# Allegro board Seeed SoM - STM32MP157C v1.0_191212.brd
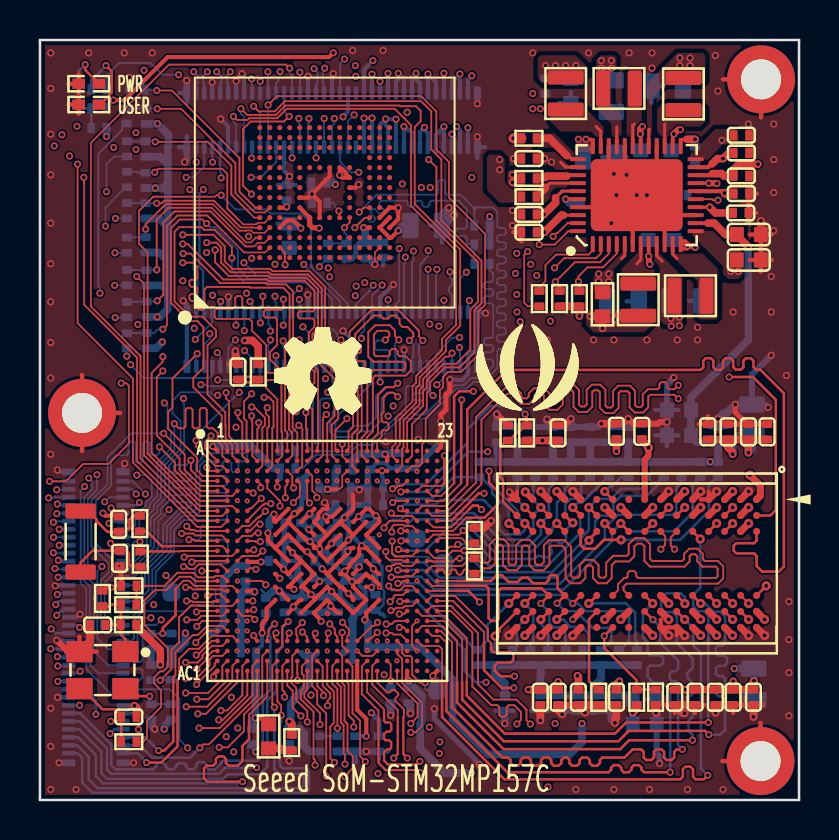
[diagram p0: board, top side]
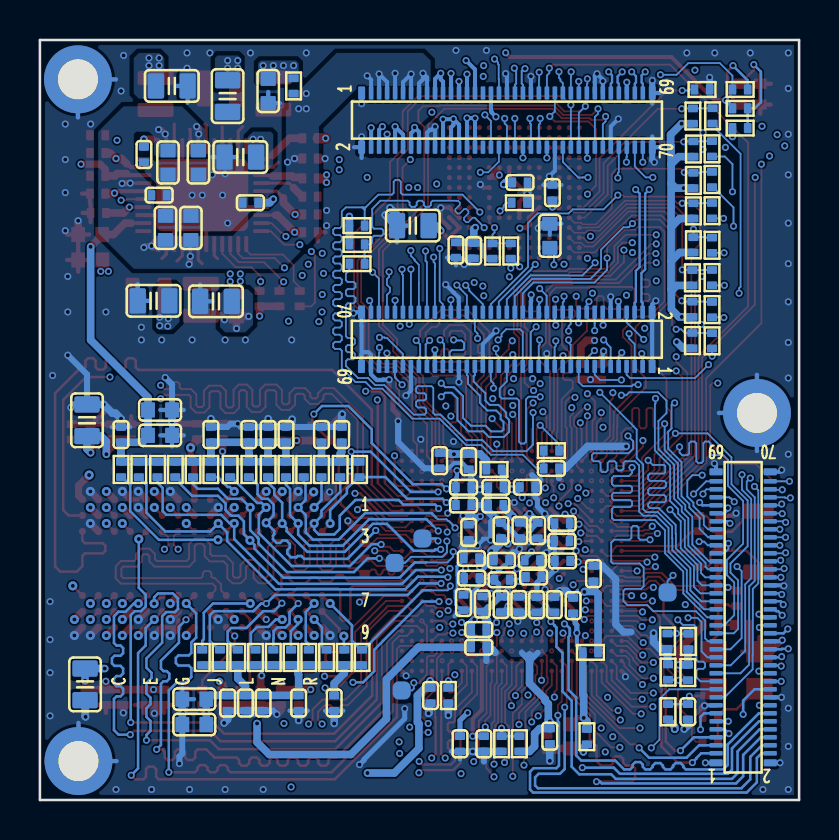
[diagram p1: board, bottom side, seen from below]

Outline 38 x 38 mm; copper layers: TOP, GND02, LAYER_3, PWR_4, LAYER_5, LAYER_6, GND7, BOTTOM. Coordinates in mm from the lower left corner of the outline.
Outline path: rectangle 38,0 0,38 ; 0,38 0,0 38,0 38,38 0,38

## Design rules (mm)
constraint set DEFAULT: min track width 0.089, pair gap 0.089
net group ADC1: nets ADC1_INN1 ADC1_INP1
net group DDR_CLK: nets DDR_CLK DDR_CLKN
net group DDR_DQS0: nets DDR_DQS0 DDR_DQSN0
net group DDR_DQS1: nets DDR_DQS1 DDR_DQSN1
net group DSI_CK: nets DSI_CK_N DSI_CK_P
net group DSI_D0: nets DSI_D0_N DSI_D0_P
net group DSI_D1: nets DSI_D1_N DSI_D1_P
net group ETH_MDC: nets ETH_MDC ETH_MDIO
net group OTG_FS: nets OTG_FS_DM OTG_FS_DP
net group USB1: nets USB1_N USB1_P
net group USB2: nets USB2_N USB2_P
net group DDR_A0: nets DDR_A0 DDR_A1 DDR_A2 DDR_A3 DDR_A4 DDR_A5 DDR_A6 DDR_A7 DDR_A8 DDR_A9 DDR_A10 DDR_A11 DDR_A12 DDR_A13 DDR_A14 DDR_BA0 DDR_BA1 DDR_BA2 DDR_CASN DDR_CKE DDR_CSN DDR_ODT DDR_RASN DDR_RESETN DDR_WEN
net group DDR_DQ0: nets DDR_D0 DDR_D1 DDR_D2 DDR_D3 DDR_D4 DDR_D5 DDR_D6 DDR_D7 DDR_DQM0
net group DDR_DQ1: nets DDR_D8 DDR_D9 DDR_D10 DDR_D11 DDR_D12 DDR_D13 DDR_D14 DDR_D15 DDR_DQM1
net group DVP: nets DVP_D0 DVP_D1 DVP_D2 DVP_D3 DVP_D4 DVP_D5 DVP_D6 DVP_D7 DVP_HSYNC DVP_PCLK DVP_VSYNC GPIO_PI3 SAI2_SDBM SPI5_MISO
net group ETH_RX: nets ETH_CLK125 ETH_RX_CLK ETH_RX_DV ETH_RXD0 ETH_RXD1 ETH_RXD2 ETH_RXD3
net group ETH_TX: nets ETH_GTX_CLK ETH_TX_EN ETH_TXD0 ETH_TXD1 ETH_TXD2 ETH_TXD3
net group LTDC: nets LTDC_B0 LTDC_B1 LTDC_B2 LTDC_B3 LTDC_B4 LTDC_B5 LTDC_B6 LTDC_B7 LTDC_CLK LTDC_DE LTDC_G0 LTDC_G1 LTDC_G2 LTDC_G3 LTDC_G4 LTDC_G5 LTDC_G6 LTDC_G7 LTDC_HSYNC LTDC_R0 LTDC_R1 LTDC_R2 LTDC_R3 LTDC_R4 LTDC_R5 LTDC_R6 LTDC_R7 LTDC_VSYNC
net group MMC2: nets MMC2_CLK MMC2_CMD MMC2_DAT0 MMC2_DAT1 MMC2_DAT2 MMC2_DAT3 MMC2_DAT4 MMC2_DAT5 MMC2_DAT6 MMC2_DAT7 N3283268
net group SDMMC1: nets SDMMC1_CK SDMMC1_CMD SDMMC1_D0 SDMMC1_D1 SDMMC1_D2 SDMMC1_D3
net group SDMMC3: nets SDMMC3_CLK SDMMC3_CMD SDMMC3_D0 SDMMC3_D1 SDMMC3_D2 SDMMC3_D3

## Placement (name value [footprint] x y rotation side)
C27  100nF  [C0402]  18.44 5.22 270 bottom
C28  1uF  [C0402]  11.87 12.94 0 bottom
C29  1uF  [C0402]  15.85 9.8 270 bottom
C30  1uF  [C0402]  11.86 13.83 0 bottom
C31  1uF  [C0402]  13.35 11.98 180 bottom
C32  1uF  [C0402]  13.08 13.47 270 bottom
C33  1uF  [C0402]  13.97 13.48 270 bottom
C34  1uF  [C0402]  14.92 13.47 90 bottom
C35  1uF  [C0402]  14.9 11.98 180 bottom
C36  1uF  [C0402]  14.92 9.78 90 bottom
C37  1uF  [C0402]  14.03 9.77 90 bottom
C38  1uF  [C0402]  12.25 9.77 90 bottom
C39  1uF  [C0402]  13.14 9.76 90 bottom
C40  1uF  [C0402]  14.87 11.01 0 bottom
C41  1uF  [C0402]  13.29 11.14 180 bottom
C42  1uF  [C0402]  16.38 11.09 180 bottom
C43  1uF  [C0402]  16.54 13.38 270 bottom
C44  1uF  [C0402]  16.8 9.87 270 bottom
C45  1uF  [C0402]  16.03 8.53 180 bottom
C46  1uF  [C0402]  11.31 9.72 90 bottom
C47  1uF  [C0402]  10.29 11.32 90 bottom
C48  1uF  [C0402]  15.78 2.81 90 bottom
C49  1uF  [C0402]  13.59 15.64 180 bottom
C50  100nF  [C0402]  15.17 15.63 0 bottom
C51  1uF  [C0402]  16.79 15.64 180 bottom
C52  100nF  [C0402]  16.97 2.81 270 bottom
C53  100nF  [C0402]  26.95 5.14 270 top
C54  100nF  [C0402]  30.13 18.43 90 top
C59  100nF  [C0402]  26.58 18.27 90 bottom
C60  100nF  [C0402]  25.05 4.85 270 bottom
C61  100nF  [C0402]  25.68 18.27 90 bottom
C62  100nF  [C0402]  27.54 18.27 90 bottom
C63  100nF  [C0402]  23.91 18.27 90 bottom
C64  100nF  [C0402]  23.27 4.85 270 bottom
C65  100nF  [C0402]  22.89 18.27 90 bottom
C66  100nF  [C0402]  28.6 4.85 270 bottom
C67  100nF  [C0402]  26.83 4.85 270 bottom
C68  100nF  [C0402]  29.44 18.27 90 bottom
C69  100nF  [C0402]  27.71 4.85 270 bottom
C70  100nF  [C0402]  33.94 18.27 90 bottom
C79  10uF  [C0805]  35.74 5.78 270 bottom
C80  100nF  [C0402]  25.94 18.35 90 top
C81  100nF  [C0402]  25.05 5.14 270 top
C82  100nF  [C0402]  28.86 18.43 90 top
C91  10uF  [C0603]  30.27 5.04 0 bottom
C92  10uF  [C0603]  30.27 3.77 0 bottom
C93  10uF  [C0603]  31.99 18.23 180 bottom
C94  10uF  [C0603]  31.99 19.5 180 bottom
C105  10nF  [C0402]  11.84 11.95 0 bottom
C106  10nF  [C0402]  5.57 4.41 90 bottom
C107  6.8pF  [C0402]  2.89 8.75 0 top
C108  6.8pF  [C0402]  4.45 4.16 0 top
C109  6.8pF  [C0402]  3.94 13.79 90 top
C110  6.8pF  [C0402]  3.99 12.08 270 top
C120  1uF  [C0402]  16.41 12.08 0 bottom
C121  1uF  [C0402]  15.18 14.75 0 bottom
C132  1uF  [C0402]  16.03 7.64 180 bottom
C133  100nF  [C0402]  9.91 21.4 270 top
C134  100nF  [C0402]  12.48 3.19 90 bottom
C137  100nF  [C0402]  16.54 16.92 270 bottom
C138  1uF  [C0402]  17.99 16.97 270 bottom
C142  100nF  [C0402]  16.79 14.75 180 bottom
C147  100nF  [C0402]  25.94 5.14 270 top
C148  100nF  [C0402]  28.86 5.14 270 top
C149  100nF  [C0402]  31.78 5.14 270 top
C150  100nF  [C0402]  32.8 5.14 270 top
C151  100nF  [C0402]  33.81 5.14 270 top
C152  100nF  [C0402]  34.7 5.14 270 top
C153  100nF  [C0402]  35.72 5.14 270 top
C154  100nF  [C0402]  36.4 18.41 90 top
C155  100nF  [C0402]  35.46 18.41 90 top
C156  100nF  [C0402]  34.45 18.41 90 top
C157  100nF  [C0402]  33.43 18.41 90 top
C162  10uF  [C0805]  35.64 18.98 90 bottom
C179  10pF  [C0402]  12.4 16.58 180 bottom
C180  2.2uF  [C0603]  12.48 28.21 90 bottom
C181  10uF  [C0805]  19.33 28.72 0 bottom
C182  100nF  [C0402]  12.35 30.37 90 bottom
C183  100nF  [C0402]  16.29 27.46 270 bottom
C184  100nF  [C0402]  13.97 30.88 180 bottom
C185  100nF  [C0402]  17.18 27.5 270 bottom
C186  10uF  [C0603]  30.45 28.6 90 bottom
C187  10uF  [C0603]  31.72 28.61 90 bottom
C188  10uF  [C0603]  30.07 31.88 270 bottom
C189  10uF  [C0603]  31.59 31.88 270 bottom
C190  10uF  [C0603]  26.57 35.45 270 bottom
C191  10uF  [C0603]  35.48 27 0 top
C192  1uF  [C0402]  35.11 33.24 0 top
C193  1uF  [C0402]  32.03 30.24 180 bottom
C194  4.7uF  [C0402]  24.48 32.07 180 top
C195  4.7uF  [C0402]  24.48 28.39 180 top
C196  22uF  [C0805]  29.19 24.93 0 bottom
C197  22uF  [C0805]  32.31 24.96 0 bottom
C198  22uF  [C0805]  28.6 35.2 270 bottom
C199  22uF  [C0805]  31.4 35.7 180 bottom
C200  22uF  [C0805]  27.97 32.15 0 bottom
C201  1uF  [C0402]  35.08 29.35 0 top
C202  10uF  [C0603]  35.49 28.27 0 top
C203  4.7uF  [C0402]  32.8 32.27 270 bottom
C204  4.7uF  [C0402]  35.11 32.35 0 top
C205  4.7uF  [C0402]  35.11 30.32 0 top
C206  4.7uF  [C0402]  35.11 31.21 0 top
C207  4.7uF  [C0402]  24.48 29.28 180 top
C208  4.7uF  [C0402]  27.46 29.86 0 bottom
J1  DF40C-70DP-0.4V(51)  [BTB2X35_0D4_15_52X1_85X1_14MM]  2.8 9.13 0 bottom
J2  DF40C-70DP-0.4V(51)  [BTB2X35_0D4_15_52X1_85X1_14MM]  14.63 23.04 270 bottom
J4  DF40C-70DP-0.4V(51)  [BTB2X35_0D4_15_52X1_85X1_14MM]  14.62 33.99 90 bottom
J5  Header 1P  [PTH_2MM_3D4]  36.07 1.95 90 top
J6  Header 1P  [PTH_2MM_3D4]  36.1 36.03 90 top
J7  Header 1P  [PTH_2MM_3D4]  2.11 19.35 90 top
L5  4.7uH  [L0603]  11.44 3.18 90 top
L8  1uH  [L2016]  26.32 35.32 270 top
L9  1uH  [L2016]  29.95 25.01 270 top
L10  1uH  [L2016]  32.56 25.21 180 top
L11  1uH  [L2016]  28.99 35.58 180 top
L12  1uH  [L2016]  32.21 35.3 90 top
LED1  Red  [LED0402]  2.45 35.81 180 top
LED2  Blue  [LED0402]  2.45 34.77 180 top
OSC1  24MHz  6.8pF  [X4-SMD-3_2X2_5X1_0MM]  3.13 6.49 180 top
R1  10K  [R0402]  4.43 8.76 180 top
R2  0R  [R0402]  5 13.82 90 top
R3  0R  [R0402]  10.93 21.4 270 top
R4  0R  [R0402]  4.45 2.91 0 top
R5  2K  [R0402]  2.95 35.53 180 bottom
R6  2K  [R0402]  2.95 33.59 180 bottom
R7  1K  [R0402]  2.95 34.59 180 bottom
R10  240R  [R0402]  21.75 13.22 90 top
R12  0R  [R0402]  12.61 2.87 270 top
R13  240R  [R0402]  27.97 5.14 270 top
R14  10K  [R0402]  30.82 5.14 90 top
R15  10K  [R0402]  23.42 18.35 90 top
R16  100R  [R0402]  21.75 11.7 90 top
R17  56R  [R0402]  26.58 16.53 90 bottom
R18  56R  [R0402]  26.32 7.13 270 bottom
R19  56R  [R0402]  25.68 16.53 90 bottom
R20  56R  [R0402]  27.54 16.53 90 bottom
R21  56R  [R0402]  25.43 7.13 270 bottom
R22  56R  [R0402]  24.79 16.53 90 bottom
R23  56R  [R0402]  23.65 7.13 270 bottom
R24  56R  [R0402]  23.91 16.53 90 bottom
R25  56R  [R0402]  22.76 7.13 270 bottom
R26  56R  [R0402]  22.97 16.53 90 bottom
R27  56R  [R0402]  29.87 7.13 270 bottom
R28  56R  [R0402]  24.54 7.13 270 bottom
R29  56R  [R0402]  28.1 7.13 270 bottom
R30  56R  [R0402]  22 16.53 90 bottom
R31  56R  [R0402]  21.87 7.13 270 bottom
R32  56R  [R0402]  28.48 16.53 90 bottom
R33  56R  [R0402]  27.21 7.13 270 bottom
R34  56R  [R0402]  33.94 16.53 90 bottom
R35  56R  [R0402]  33.05 16.53 90 bottom
R36  56R  [R0402]  32.11 16.53 90 bottom
R37  56R  [R0402]  30.34 16.53 90 bottom
R38  56R  [R0402]  29.87 5.14 270 top
R39  56R  [R0402]  31.22 16.53 90 bottom
R40  56R  [R0402]  29.45 16.53 90 bottom
R79  0R  [R0402]  5.03 12.05 90 top
R80  3.3K  [R0402]  17.56 5.22 270 bottom
R81  0R  [R0402]  14 2.81 270 bottom
R82  0R  [R0402]  14.89 2.81 270 bottom
R83  0R  [R0402]  5.54 7.93 270 bottom
R84  0R  [R0402]  5.57 6.37 90 bottom
R85  0R  [R0402]  6.58 7.94 90 bottom
R86  0R  [R0402]  6.56 6.39 270 bottom
R87  10R  [R0402]  6.56 4.41 90 bottom
R88  10K  [R0402]  3.13 10.08 270 top
R89  1K  [R0402]  4.45 10.71 0 top
R90  0R  [R0402]  4.44 9.77 0 top
R93  0R  [R0402]  10.62 3.17 90 bottom
R94  0R  [R0402]  10.44 7.38 180 bottom
R95  0R  [R0402]  15.27 16.53 180 bottom
R102  1.5K  [R0402]  24.36 18.35 270 top
R119  56R  [R0402]  28.99 7.13 270 bottom
R125  33R  [R0402]  4.36 26.12 90 bottom
R126  33R  [R0402]  4.36 29.46 90 bottom
R127  33R  [R0402]  4.36 32.56 90 bottom
R128  33R  [R0402]  4.36 22.96 90 bottom
R129  33R  [R0402]  4.36 24.52 90 bottom
R130  33R  [R0402]  4.36 27.74 90 bottom
R131  33R  [R0402]  4.36 31.02 90 bottom
R132  33R  [R0402]  4.33 34.2 90 bottom
R133  33R  [R0402]  22.13 26.81 180 bottom
R134  33R  [R0402]  12.4 17.47 0 bottom
R135  33R  [R0402]  14.43 27.45 90 bottom
R136  10K  [R0402]  5.34 26.11 90 bottom
R137  10K  [R0402]  5.29 29.46 90 bottom
R138  10K  [R0402]  5.29 32.55 90 bottom
R139  10K  [R0402]  5.34 22.97 90 bottom
R140  10K  [R0402]  5.34 24.54 90 bottom
R141  10K  [R0402]  5.29 27.76 90 bottom
R142  10K  [R0402]  5.29 30.98 90 bottom
R143  10K  [R0402]  5.31 34.2 90 bottom
R144  10K  [R0402]  22.13 27.78 180 bottom
R145  10K  [R0402]  22.13 28.72 180 bottom
R146  10K  [R0402]  15.35 27.45 90 bottom
R147  0R  [R0402]  4.86 35.53 180 bottom
R148  0R  [R0402]  14 29.86 180 bottom
R149  0R  [R0402]  25.3 35.7 90 bottom
R150  0R  [R0402]  24.48 31.08 0 top
R151  4.7K  [R0402]  27.01 25.07 90 top
R152  4.7K  [R0402]  26.01 25.07 90 top
R153  0R  [R0402]  25 25.07 90 top
R154  0R  [R0603]  28.16 24.78 90 top
R155  0R  [R0402]  24.48 33.09 180 top
R156  0R  [R0402]  24.48 30.17 180 top
TP101  Test TP35S_SMD  [TP35S_SMD]  6.58 10.38 270 bottom
TP102  Test TP35S_SMD  [TP35S_SMD]  19.89 5.48 270 bottom
TP103  Test TP35S_SMD  [TP35S_SMD]  18.85 13.07 270 bottom
TP104  Test TP35S_SMD  [TP35S_SMD]  20.25 11.85 270 bottom
U2  STPMIC1APQR  [WFQFN44_0D4_5X6X0_8MM]  29.87 30.24 90 top
U3  STM32MP157CAC3  [TFBGA361_0D5_12X12X1_2MM]  14.38 11.95 0 top
U6  MT41K256M16TW-107:P  [BGA96_T9_P8_9X14]  29.87 11.83 270 top
U8  EMMC04G-M627  [BGA153_P14_P5_11P5X13]  14.25 30.37 90 top
X1  32.768kHz 12.5pF  [X2_SMD_3_2X1_5MM]  2.04 12.92 270 top

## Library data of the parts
C27-C54 C59-C70 C79-C82 C91-C94 C105-C110 C120 C121 C132-C134 C137 C138 C142 C147-C157 C162 C179-C208 = CC
J1 J2 J4 = Header 2X35+4p
J5-J7 = Header 1P
L5 L8-L12 = L
LED1 LED2 = Single LED
OSC1 = OSC_4P
R1-R7 R10 R12-R40 R79-R90 R93-R95 R102 R119 R125-R156 = R
TP101-TP104 = TEST_POINT
U2 = STPMIC1APQR
U3 = STM32MP157CAC3
U6 = DDR3_96-ball_FBGA
U8 = eMMC_153-ball_WFBGA
X1 = XTAL_2P

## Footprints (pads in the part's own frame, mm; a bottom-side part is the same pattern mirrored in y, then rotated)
BGA96_T9_P8_9X14
  round 0.356 smd: A1(-3.2,6.001) A2(-2.4,6.001) A3(-1.6,6.001) A7(1.6,6.001) A8(2.4,6.001) A9(3.2,6.001) B1(-3.2,5.201) B2(-2.4,5.201) B3(-1.6,5.201) B7(1.6,5.201) B8(2.4,5.201) B9(3.2,5.201) C1(-3.2,4.401) C2(-2.4,4.401) C3(-1.6,4.401) C7(1.6,4.401) C8(2.4,4.401) C9(3.2,4.401) D1(-3.2,3.6) D2(-2.4,3.6) D3(-1.6,3.6) D7(1.6,3.6) D8(2.4,3.6) D9(3.2,3.6) E1(-3.2,2.8) E2(-2.4,2.8) E3(-1.6,2.8) E7(1.6,2.8) E8(2.4,2.8) E9(3.2,2.8) F1(-3.2,2) F2(-2.4,2) F3(-1.6,2) F7(1.6,2) F8(2.4,2) F9(3.2,2) G1(-3.2,1.2) G2(-2.4,1.2) G3(-1.6,1.2) G7(1.6,1.2) G8(2.4,1.2) G9(3.2,1.2) H1(-3.2,0.4) H2(-2.4,0.4) H3(-1.6,0.4) H7(1.6,0.4) H8(2.4,0.4) H9(3.2,0.4) J1(-3.2,-0.4) J2(-2.4,-0.4) J3(-1.6,-0.4) J7(1.6,-0.4) J8(2.4,-0.4) J9(3.2,-0.4) K1(-3.2,-1.2) K2(-2.4,-1.2) K3(-1.6,-1.2) K7(1.6,-1.2) K8(2.4,-1.2) K9(3.2,-1.2) L1(-3.2,-2) L2(-2.4,-2) L3(-1.6,-2) L7(1.6,-2) L8(2.4,-2) L9(3.2,-2) M1(-3.2,-2.8) M2(-2.4,-2.8) M3(-1.6,-2.8) M7(1.6,-2.8) M8(2.4,-2.8) M9(3.2,-2.8) N1(-3.2,-3.6) N2(-2.4,-3.6) N3(-1.6,-3.6) N7(1.6,-3.6) N8(2.4,-3.6) N9(3.2,-3.6) P1(-3.2,-4.401) P2(-2.4,-4.401) P3(-1.6,-4.401) P7(1.6,-4.401) P8(2.4,-4.401) P9(3.2,-4.401) R1(-3.2,-5.201) R2(-2.4,-5.201) R3(-1.6,-5.201) R7(1.6,-5.201) R8(2.4,-5.201) R9(3.2,-5.201) T1(-3.2,-6.001) T2(-2.4,-6.001) T3(-1.6,-6.001) T7(1.6,-6.001) T8(2.4,-6.001) T9(3.2,-6.001)
BGA153_P14_P5_11P5X13
  round 0.254 smd: A1(-3.25,3.25) A2(-2.75,3.25) A3(-2.25,3.25) A4(-1.75,3.25) A5(-1.25,3.25) A6(-0.75,3.25) A7(-0.25,3.25) A8(0.25,3.25) A9(0.75,3.25) A10(1.25,3.25) A11(1.75,3.25) A12(2.25,3.25) A13(2.75,3.25) A14(3.25,3.25) B1(-3.25,2.75) B2(-2.75,2.75) B3(-2.25,2.75) B4(-1.75,2.75) B5(-1.25,2.75) B6(-0.75,2.75) B7(-0.25,2.75) B8(0.25,2.75) B9(0.75,2.75) B10(1.25,2.75) B11(1.75,2.75) B12(2.25,2.75) B13(2.75,2.75) B14(3.25,2.75) C1(-3.25,2.25) C2(-2.75,2.25) C3(-2.25,2.25) C4(-1.75,2.25) C5(-1.25,2.25) C6(-0.75,2.25) C7(-0.25,2.25) C8(0.25,2.25) C9(0.75,2.25) C10(1.25,2.25) C11(1.75,2.25) C12(2.25,2.25) C13(2.75,2.25) C14(3.25,2.25) D1(-3.25,1.75) D2(-2.75,1.75) D3(-2.25,1.75) D4(-1.75,1.75) D12(2.25,1.75) D13(2.75,1.75) D14(3.25,1.75) E1(-3.25,1.25) E2(-2.75,1.25) E3(-2.25,1.25) E5(-1.25,1.25) E6(-0.75,1.25) E7(-0.25,1.25) E8(0.25,1.25) E9(0.75,1.25) E10(1.25,1.25) E12(2.25,1.25) E13(2.75,1.25) E14(3.25,1.25) F1(-3.25,0.75) F2(-2.75,0.75) F3(-2.25,0.75) F5(-1.25,0.75) F10(1.25,0.75) F12(2.25,0.75) F13(2.75,0.75) F14(3.25,0.75) G1(-3.25,0.25) G2(-2.75,0.25) G3(-2.25,0.25) G5(-1.25,0.25) G10(1.25,0.25) G12(2.25,0.25) G13(2.75,0.25) G14(3.25,0.25) H1(-3.25,-0.25) H2(-2.75,-0.25) H3(-2.25,-0.25) H5(-1.25,-0.25) H10(1.25,-0.25) H12(2.25,-0.25) H13(2.75,-0.25) H14(3.25,-0.25) J1(-3.25,-0.75) J2(-2.75,-0.75) J3(-2.25,-0.75) J5(-1.25,-0.75) J10(1.25,-0.75) J12(2.25,-0.75) J13(2.75,-0.75) J14(3.25,-0.75) K1(-3.25,-1.25) K2(-2.75,-1.25) K3(-2.25,-1.25) K5(-1.25,-1.25) K6(-0.75,-1.25) K7(-0.25,-1.25) K8(0.25,-1.25) K9(0.75,-1.25) K10(1.25,-1.25) K12(2.25,-1.25) K13(2.75,-1.25) K14(3.25,-1.25) L1(-3.25,-1.75) L2(-2.75,-1.75) L3(-2.25,-1.75) L12(2.25,-1.75) L13(2.75,-1.75) L14(3.25,-1.75) M1(-3.25,-2.25) M2(-2.75,-2.25) M3(-2.25,-2.25) M4(-1.75,-2.25) M5(-1.25,-2.25) M6(-0.75,-2.25) M7(-0.25,-2.25) M8(0.25,-2.25) M9(0.75,-2.25) M10(1.25,-2.25) M11(1.75,-2.25) M12(2.25,-2.25) M13(2.75,-2.25) M14(3.25,-2.25) N1(-3.25,-2.75) N2(-2.75,-2.75) N3(-2.25,-2.75) N4(-1.75,-2.75) N5(-1.25,-2.75) N6(-0.75,-2.75) N7(-0.25,-2.75) N8(0.25,-2.75) N9(0.75,-2.75) N10(1.25,-2.75) N11(1.75,-2.75) N12(2.25,-2.75) N13(2.75,-2.75) N14(3.25,-2.75) P1(-3.25,-3.25) P2(-2.75,-3.25) P3(-2.25,-3.25) P4(-1.75,-3.25) P5(-1.25,-3.25) P6(-0.75,-3.25) P7(-0.25,-3.25) P8(0.25,-3.25) P9(0.75,-3.25) P10(1.25,-3.25) P11(1.75,-3.25) P12(2.25,-3.25) P13(2.75,-3.25) P14(3.25,-3.25)
BTB2X35_0D4_15_52X1_85X1_14MM
  rrect 0.66x0.23 smd: 1(1.355,6.8) 2(-1.355,6.8) 3(1.355,6.4) 4(-1.355,6.4) 5(1.355,6) 6(-1.355,6) 7(1.355,5.6) 8(-1.355,5.6) 9(1.355,5.2) 10(-1.355,5.2) 11(1.355,4.8) 12(-1.355,4.8) 13(1.355,4.4) 14(-1.355,4.4) 15(1.355,4) 16(-1.355,4) 17(1.355,3.6) 18(-1.355,3.6) 19(1.355,3.2) 20(-1.355,3.2) 21(1.355,2.8) 22(-1.355,2.8) 23(1.355,2.4) 24(-1.355,2.4) 25(1.355,2) 26(-1.355,2) 27(1.355,1.6) 28(-1.355,1.6) 29(1.355,1.2) 30(-1.355,1.2) 31(1.355,0.8) 32(-1.355,0.8) 33(1.355,0.4) 34(-1.355,0.4) 35(1.355,0) 36(-1.355,0) 37(1.355,-0.4) 38(-1.355,-0.4) 39(1.355,-0.8) 40(-1.355,-0.8) 41(1.355,-1.2) 42(-1.355,-1.2) 43(1.355,-1.6) 44(-1.355,-1.6) 45(1.355,-2) 46(-1.355,-2) 47(1.355,-2.4) 48(-1.355,-2.4) 49(1.355,-2.8) 50(-1.355,-2.8) 51(1.355,-3.2) 52(-1.355,-3.2) 53(1.355,-3.6) 54(-1.355,-3.6) 55(1.355,-4) 56(-1.355,-4) 57(1.355,-4.4) 58(-1.355,-4.4) 59(1.355,-4.8) 60(-1.355,-4.8) 61(1.355,-5.2) 62(-1.355,-5.2) 63(1.355,-5.6) 64(-1.355,-5.6) 65(1.355,-6) 66(-1.355,-6) 67(1.355,-6.4) 68(-1.355,-6.4) 69(1.355,-6.8) 70(-1.355,-6.8)
  rrect 0.66x0.35 smd: 71(1.355,-7.275) 72(-1.355,-7.275) 73(1.355,7.275) 74(-1.355,7.275)
C0402
  rrect 0.385x0.508 smd: 1(-0.383,0) 2(0.383,0)
C0603
  rrect 0.696x0.762 smd: 1(-0.602,0) 2(0.602,0)
C0805
  rrect 0.819x1.27 smd: 1(-0.79,0) 2(0.79,0)
L0603
  rrect 0.696x0.762 smd: 1(-0.602,0) 2(0.602,0)
L2016
  rrect 0.7x1.8 smd: 1(-0.8,0) 2(0.8,0)
LED0402
  rect 0.635x0.508 smd: 1(-0.508,0) 2(0.508,0)
PTH_2MM_3D4
  round 3.4 hole 2: 1(0,0)
R0402
  rrect 0.385x0.508 smd: 1(-0.383,0) 2(0.383,0)
R0603
  rrect 0.696x0.762 smd: 1(-0.602,0) 2(0.602,0)
TFBGA361_0D5_12X12X1_2MM
  round 0.23 smd: 1A2(-1.95,2.6) 1A3(-1.3,2.6) 1A4(-0.65,2.6) 1A5(0,2.6) 1A6(0.65,2.6) 1A7(1.3,2.6) 1A8(1.95,2.6) 1B1(-2.6,1.95) 1B2(-1.95,1.95) 1B3(-1.3,1.95) 1B4(-0.65,1.95) 1B5(0,1.95) 1B6(0.65,1.95) 1B7(1.3,1.95) 1B8(1.95,1.95) 1B9(2.6,1.95) 1C1(-2.6,1.3) 1C2(-1.95,1.3) 1C3(-1.3,1.3) 1C4(-0.65,1.3) 1C5(0,1.3) 1C6(0.65,1.3) 1C7(1.3,1.3) 1C8(1.95,1.3) 1C9(2.6,1.3) 1D1(-2.6,0.65) 1D2(-1.95,0.65) 1D3(-1.3,0.65) 1D4(-0.65,0.65) 1D5(0,0.65) 1D6(0.65,0.65) 1D7(1.3,0.65) 1D8(1.95,0.65) 1D9(2.6,0.65) 1E1(-2.6,0) 1E2(-1.95,0) 1E3(-1.3,0) 1E4(-0.65,0) 1E5(0,0) 1E6(0.65,0) 1E7(1.3,0) 1E8(1.95,0) 1E9(2.6,0) 1F1(-2.6,-0.65) 1F2(-1.95,-0.65) 1F3(-1.3,-0.65) 1F4(-0.65,-0.65) 1F5(0,-0.65) 1F6(0.65,-0.65) 1F7(1.3,-0.65) 1F8(1.95,-0.65) 1F9(2.6,-0.65) 1G1(-2.6,-1.3) 1G2(-1.95,-1.3) 1G3(-1.3,-1.3) 1G4(-0.65,-1.3) 1G5(0,-1.3) 1G6(0.65,-1.3) 1G7(1.3,-1.3) 1G8(1.95,-1.3) 1G9(2.6,-1.3) 1H1(-2.6,-1.95) 1H2(-1.95,-1.95) 1H3(-1.3,-1.95) 1H4(-0.65,-1.95) 1H5(0,-1.95) 1H6(0.65,-1.95) 1H7(1.3,-1.95) 1H8(1.95,-1.95) 1H9(2.6,-1.95) 1J2(-1.95,-2.6) 1J3(-1.3,-2.6) 1J4(-0.65,-2.6) 1J5(0,-2.6) 1J6(0.65,-2.6) 1J7(1.3,-2.6) 1J8(1.95,-2.6) A1(-5.5,5.5) A2(-5,5.5) A3(-4.5,5.5) A4(-4,5.5) A5(-3.5,5.5) A7(-2.5,5.5) A8(-2,5.5) A10(-1,5.5) A11(-0.5,5.5) A13(0.5,5.5) A14(1,5.5) A16(2,5.5) A17(2.5,5.5) A19(3.5,5.5) A20(4,5.5) A21(4.5,5.5) A22(5,5.5) A23(5.5,5.5) AA1(-5.5,-4.5) AA2(-5,-4.5) AA3(-4.5,-4.5) AA4(-4,-4.5) AA5(-3.5,-4.5) AA6(-3,-4.5) AA7(-2.5,-4.5) AA8(-2,-4.5) AA9(-1.5,-4.5) AA10(-1,-4.5) AA11(-0.5,-4.5) AA12(0,-4.5) AA13(0.5,-4.5) AA14(1,-4.5) AA15(1.5,-4.5) AA16(2,-4.5) AA17(2.5,-4.5) AA18(3,-4.5) AA19(3.5,-4.5) AA20(4,-4.5) AA21(4.5,-4.5) AA22(5,-4.5) AA23(5.5,-4.5) AB1(-5.5,-5) AB2(-5,-5) AB3(-4.5,-5) AB4(-4,-5) AB5(-3.5,-5) AB6(-3,-5) AB7(-2.5,-5) AB8(-2,-5) AB9(-1.5,-5) AB10(-1,-5) AB11(-0.5,-5) AB12(0,-5) AB13(0.5,-5) AB14(1,-5) AB15(1.5,-5) AB16(2,-5) AB17(2.5,-5) AB18(3,-5) AB19(3.5,-5) AB20(4,-5) AB21(4.5,-5) AB22(5,-5) AB23(5.5,-5) AC1(-5.5,-5.5) AC2(-5,-5.5) AC3(-4.5,-5.5) AC4(-4,-5.5) AC5(-3.5,-5.5) AC7(-2.5,-5.5) AC8(-2,-5.5) AC10(-1,-5.5) AC11(-0.5,-5.5) AC13(0.5,-5.5) AC14(1,-5.5) AC16(2,-5.5) AC17(2.5,-5.5) AC19(3.5,-5.5) AC20(4,-5.5) AC21(4.5,-5.5) AC22(5,-5.5) AC23(5.5,-5.5) B1(-5.5,5) B2(-5,5) B3(-4.5,5) B4(-4,5) B5(-3.5,5) B6(-3,5) B7(-2.5,5) B8(-2,5) B9(-1.5,5) B10(-1,5) B11(-0.5,5) B12(0,5) B13(0.5,5) B14(1,5) B15(1.5,5) B16(2,5) B17(2.5,5) B18(3,5) B19(3.5,5) B20(4,5) B21(4.5,5) B22(5,5) B23(5.5,5) C1(-5.5,4.5) C2(-5,4.5) C3(-4.5,4.5) C4(-4,4.5) C5(-3.5,4.5) C6(-3,4.5) C7(-2.5,4.5) C8(-2,4.5) C9(-1.5,4.5) C10(-1,4.5) C11(-0.5,4.5) C12(0,4.5) C13(0.5,4.5) C14(1,4.5) C15(1.5,4.5) C16(2,4.5) C17(2.5,4.5) C18(3,4.5) C19(3.5,4.5) C20(4,4.5) C21(4.5,4.5) C22(5,4.5) C23(5.5,4.5) D1(-5.5,4) D2(-5,4) D3(-4.5,4) D4(-4,4) D5(-3.5,4) D6(-3,4) D7(-2.5,4) D8(-2,4) D9(-1.5,4) D10(-1,4) D11(-0.5,4) D12(0,4) D13(0.5,4) D14(1,4) D15(1.5,4) D16(2,4) D17(2.5,4) D18(3,4) D19(3.5,4) D20(4,4) D21(4.5,4) D22(5,4) D23(5.5,4) E1(-5.5,3.5) E2(-5,3.5) E3(-4.5,3.5) E4(-4,3.5) E20(4,3.5) E21(4.5,3.5) E22(5,3.5) E23(5.5,3.5) F2(-5,3) F3(-4.5,3) F4(-4,3) F20(4,3) F21(4.5,3) F22(5,3) G1(-5.5,2.5) G2(-5,2.5) G3(-4.5,2.5) G4(-4,2.5) G20(4,2.5) G21(4.5,2.5) G22(5,2.5) G23(5.5,2.5) H1(-5.5,2) H2(-5,2) H3(-4.5,2) H4(-4,2) H20(4,2) H21(4.5,2) H22(5,2) H23(5.5,2) J2(-5,1.5) J3(-4.5,1.5) J4(-4,1.5) J20(4,1.5) J21(4.5,1.5) J22(5,1.5) K1(-5.5,1) K2(-5,1) K3(-4.5,1) K4(-4,1) K20(4,1) K21(4.5,1) K22(5,1) K23(5.5,1) L1(-5.5,0.5) L2(-5,0.5) L3(-4.5,0.5) L4(-4,0.5) L20(4,0.5) L21(4.5,0.5) L22(5,0.5) L23(5.5,0.5) M2(-5,0) M3(-4.5,0) M4(-4,0) M20(4,0) M21(4.5,0) M22(5,0) N1(-5.5,-0.5) N2(-5,-0.5) N3(-4.5,-0.5) N4(-4,-0.5) N20(4,-0.5) N21(4.5,-0.5) N22(5,-0.5) N23(5.5,-0.5) P1(-5.5,-1) P2(-5,-1) P3(-4.5,-1) P4(-4,-1) P20(4,-1) P21(4.5,-1) P22(5,-1) P23(5.5,-1) R2(-5,-1.5) R3(-4.5,-1.5) R4(-4,-1.5) R20(4,-1.5) R21(4.5,-1.5) R22(5,-1.5) T1(-5.5,-2) T2(-5,-2) T3(-4.5,-2) T4(-4,-2) T20(4,-2) T21(4.5,-2) T22(5,-2) T23(5.5,-2) U1(-5.5,-2.5) U2(-5,-2.5) U3(-4.5,-2.5) U4(-4,-2.5) U20(4,-2.5) U21(4.5,-2.5) U22(5,-2.5) U23(5.5,-2.5) V2(-5,-3) V3(-4.5,-3) V4(-4,-3) V20(4,-3) V21(4.5,-3) V22(5,-3) W1(-5.5,-3.5) W2(-5,-3.5) W3(-4.5,-3.5) W4(-4,-3.5) W20(4,-3.5) W21(4.5,-3.5) W22(5,-3.5) W23(5.5,-3.5) Y1(-5.5,-4) Y2(-5,-4) Y3(-4.5,-4) Y4(-4,-4) Y5(-3.5,-4) Y6(-3,-4) Y7(-2.5,-4) Y8(-2,-4) Y9(-1.5,-4) Y10(-1,-4) Y11(-0.5,-4) Y12(0,-4) Y13(0.5,-4) Y14(1,-4) Y15(1.5,-4) Y16(2,-4) Y17(2.5,-4) Y18(3,-4) Y19(3.5,-4) Y20(4,-4) Y21(4.5,-4) Y22(5,-4) Y23(5.5,-4)
TP35S_SMD
  rrect 0.9x0.9 smd: 1(0,0)
WFQFN44_0D4_5X6X0_8MM
  rrect 0.8x0.2 smd: 1(-2.45,2.2) 2(-2.45,1.8) 3(-2.45,1.4) 4(-2.45,1) 5(-2.45,0.6) 6(-2.45,0.2) 7(-2.45,-0.2) 8(-2.45,-0.6) 9(-2.45,-1) 10(-2.45,-1.4) 11(-2.45,-1.8) 12(-2.45,-2.2) 23(2.45,-2.2) 24(2.45,-1.8) 25(2.45,-1.4) 26(2.45,-1) 27(2.45,-0.6) 28(2.45,-0.2) 29(2.45,0.2) 30(2.45,0.6) 31(2.45,1) 32(2.45,1.4) 33(2.45,1.8) 34(2.45,2.2)
  rrect 0.2x0.8 smd: 13(-1.8,-2.95) 14(-1.4,-2.95) 15(-1,-2.95) 16(-0.6,-2.95) 17(-0.2,-2.95) 18(0.2,-2.95) 19(0.6,-2.95) 20(1,-2.95) 21(1.4,-2.95) 22(1.8,-2.95) 35(1.8,2.95) 36(1.4,2.95) 37(1,2.95) 38(0.6,2.95) 39(0.2,2.95) 40(-0.2,2.95) 41(-0.6,2.95) 42(-1,2.95) 43(-1.4,2.95) 44(-1.8,2.95)
  rrect 3.6x4.6 smd: 45(0,0)
X2_SMD_3_2X1_5MM
  rrect 0.762x1.524 smd: 1(-1.524,0) 2(1.524,0)
X4-SMD-3_2X2_5X1_0MM
  rect 1.321x1.067 smd: 1(-1.15,-0.925) 2(1.15,-0.925) 3(1.15,0.925) 4(-1.15,0.925)

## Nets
1V2_HDMI: C204.1 J4.25 U2.21
1V8_AUDIO: C203.1 J4.23 U2.23
3V3: C192.1 C199.1 J4.2 J4.4 J4.6 J4.8 J4.10 L12.2 R7.1 U2.22 U2.27 U8.E6 U8.F5 U8.J10 U8.K9
3V3_HDMI: C205.1 J4.27 U2.18
5V_VIN: C186.1 C187.1 C188.1 C189.1 C193.1 C194.1 J4.1 J4.3 J4.5 J4.7 J4.9 J4.11 J4.13 J4.15 R149.1 U2.8 U2.12 U2.19 U2.24 U2.28 U2.36
GND: C27.2 C28.2 C29.2 C30.2 C31.2 C32.2 C33.2 C34.2 C35.2 C36.2 C37.2 C38.2 C39.2 C40.2 C41.2 C42.2 C43.2 C44.2 C45.2 C46.2 C47.2 C48.1 C49.2 C50.2 C51.2 C52.2 C53.2 C54.2 C59.2 C60.2 C61.2 C62.2 C63.2 C64.2 C65.2 C66.2 C67.2 C68.2 C69.2 C70.2 C79.2 C80.2 C81.2 C82.2 C91.2 C92.2 C93.2 C94.2 C105.2 C106.1 C107.1 C108.2 C109.2 C110.2 C120.2 C121.2 C132.2 C133.1 C134.1 C137.2 C138.2 C142.2 C147.2 C148.2 C149.2 C150.2 C151.2 C152.2 C153.2 C154.2 C155.2 C156.2 C157.2 C162.2 C179.2 C180.2 C181.2 C182.2 C183.2 C184.2 C185.2 C186.2 C187.2 C188.2 C189.2 C190.2 C191.2 C192.2 C193.2 C194.2 C195.2 C196.2 C197.2 C198.2 C199.2 C200.2 C201.2 C202.2 C203.2 C204.2 C205.2 C206.2 C207.2 C208.2 J1.13 J1.16 J1.30 J1.36 J1.44 J1.71 J1.72(PAD3) J1.73 J1.74 J2.10 J2.11 J2.25 J2.30 J2.41 J2.47 J2.48 J2.53 J2.59 J2.69 J2.71 J2.72(PAD3) J2.73 J2.74 J4.35 J4.41 J4.48 J4.57 J4.59 J4.62 J4.65 J4.71 J4.72(PAD3) J4.73 J4.74 J5.1 J6.1 J7.1 LED1.2(C) LED2.2(C) OSC1.2 R10.2 R13.2 R14.1 R15.2 R80.2 R82.2 R85.1 R86.1 R89.1 R147.2 R148.2 U2.6 U2.10 U2.15 U2.26 U2.30 U2.32 U2.41 U2.45 U3.1A3 U3.1A5 U3.1A7 U3.1B2 U3.1B4 U3.1B6 U3.1B8 U3.1C1 U3.1C3 U3.1C5 U3.1C7 U3.1C9 U3.1D2 U3.1D4 U3.1D6 U3.1D8 U3.1E1 U3.1E3 U3.1E5 U3.1E7 U3.1E9 U3.1F2 U3.1F4 U3.1F6 U3.1F8 U3.1G1 U3.1G3 U3.1G5 U3.1G7 U3.1G9 U3.1H2 U3.1H4 U3.1H6 U3.1H8 U3.1J3 U3.1J5 U3.1J7 U3.A1 U3.A23 U3.AA5 U3.AA8 U3.AA12 U3.AA16 U3.AA21 U3.AC1 U3.AC23 U3.C7 U3.C12 U3.C16 U3.C21 U3.D4 U3.F21 U3.H3 U3.K21 U3.P3 U3.P21 U3.V21 U3.W3 U6.A9 U6.B1 U6.B3 U6.B9 U6.D1 U6.D8 U6.E1 U6.E2 U6.E8 U6.F9 U6.G1 U6.G8 U6.G9 U6.J2 U6.J8 U6.M1 U6.M9 U6.P1 U6.P9 U6.T1 U6.T9 U8.C4(VSSQ4) U8.E7 U8.G5 U8.H10 U8.K8 U8.N2 U8.N5 U8.P4 U8.P6
VBAT: C133.2 J4.26 J4.28 R3.2 U3.1F1
VBUS_OTG: J4.16 J4.18 R155.2
VBUS_SW: J4.20 J4.22 J4.24 R156.2
VDD: C36.1 C37.1 C38.1 C39.1 C40.1 C41.1 C134.2 C137.1 C138.1 C181.1 C182.1 C183.1 C184.1 C185.1 C195.1 C198.1 J4.12 J4.14 L11.2 R1.1 R3.1 R6.1 R12.1 R81.2 R83.2 R84.2 R87.1 R95.1 R136.1 R137.1 R138.1 R139.1 R140.1 R141.1 R142.1 R143.1 R144.1 R145.1 R146.1 R151.1 R152.1 U2.31 U2.42 U3.1F3 U3.1G2 U3.1G4 U3.1H3 U3.1H5 U3.1J2 U3.1J4 U3.1J6 U3.B18 U8.C6 U8.M4 U8.N4 U8.P3 U8.P5
VDD_CORE: C28.1 C29.1 C30.1 C31.1 C32.1 C33.1 C34.1 C35.1 C120.1 C121.1 R154.2 U2.5 U3.1A2 U3.1A4 U3.1A6 U3.1B1 U3.1B3 U3.1B5 U3.1C2 U3.1C4 U3.1C6 U3.1D1 U3.1D3 U3.1D5 U3.1D7 U3.1E2 U3.1E4 U3.1E6 U3.1F5 U3.1F7 U3.1G6 U3.1H7
VDD_USB: C52.1 C207.1 U2.39 U3.AA15 U3.AA17
VDDA: C206.1 R93.1 U2.20
VDDQ_DDR: C42.1 C43.1 C44.1 C45.1 C79.1 C80.1 C81.1 C82.1 C132.1 C147.1 C148.1 C149.1 C150.1 C151.1 C152.1 C153.1 C154.1 C155.1 C156.1 C157.1 C162.1 C191.1 C197.1 L10.2 R102.2 U2.9 U2.13 U3.1A8 U3.1B7 U3.1B9 U3.1C8 U3.1D9 U3.1E8 U3.1F9 U3.1G8 U3.1H9 U3.1J8 U6.A1 U6.A8 U6.B2 U6.C1 U6.C9 U6.D2 U6.D9 U6.E9 U6.F1 U6.G7 U6.H2 U6.H9 U6.K2 U6.K8 U6.N1 U6.N9 U6.R1 U6.R9
ADC1_INN1: J4.37 U3.U3
ADC1_INP1: J4.39 U3.U4
ADC2_INP2: J4.33 U3.Y5
AUDIO_RST: J2.23 U3.Y13
BOOT0: J2.5 U3.N1
BOOT1: J2.7 U3.N4
BOOT2: J2.9 U3.M2
BST_OUT: C200.1 J4.17 J4.19 J4.21 R150.1 U2.34
DDR_A0: R17.1 U3.L20 U6.N3
DDR_A1: R18.1 U3.P22 U6.P7
DDR_A2: R19.1 U3.J20 U6.P3
DDR_A3: R20.1 U3.K22 U6.N2
DDR_A4: R21.1 U3.V20 U6.P8
DDR_A5: R22.1 U3.H20 U6.P2
DDR_A6: R23.1 U3.W20 U6.R8
DDR_A7: R24.1 U3.E20 U6.R2
DDR_A8: R25.1 U3.Y20 U6.T8
DDR_A9: R26.1 U3.G20 U6.R3
DDR_A10: R27.1 U3.R22 U6.L7
DDR_A11: R28.1 U3.R20 U6.R7
DDR_A12: R29.1 U3.P23 U6.N7
DDR_A13: R30.1 U3.F20 U6.T3
DDR_A14: R31.1 U3.R21 U6.T7
DDR_A15: R119.1 U3.P20 U6.M7
DDR_BA0: R32.1 U3.L23 U6.M2
DDR_BA1: R33.1 U3.U20 U6.N8
DDR_BA2: R34.1 U3.M21 U6.M3
DDR_CASN: R36.1 U3.N20 U6.K3
DDR_CKE: R14.2 R38.1 U3.T20 U6.K9
DDR_CLK: R16.2 U3.N22 U6.J7
DDR_CLKN: R16.1 U3.N23 U6.K7
DDR_CSN: R37.1 U3.M22 U6.L2
DDR_D0: U3.E22 U6.A2
DDR_D1: U3.F22 U6.C3
DDR_D2: U3.H21 U6.A7
DDR_D3: U3.E21 U6.C2
DDR_D4: U3.J21 U6.B8
DDR_D5: U3.J22 U6.C8
DDR_D6: U3.H22 U6.D7
DDR_D7: U3.G21 U6.A3
DDR_D8: U3.T21 U6.F2
DDR_D9: U3.U21 U6.E3
DDR_D10: U3.T22 U6.G2
DDR_D11: U3.W21 U6.F7
DDR_D12: U3.W23 U6.H8
DDR_D13: U3.T23 U6.H3
DDR_D14: U3.W22 U6.H7
DDR_D15: U3.Y21 U6.F8
DDR_DQM0: U3.H23 U6.D3
DDR_DQM1: U3.V22 U6.E7
DDR_DQS0: U3.G22 U6.C7
DDR_DQS1: U3.U22 U6.F3
DDR_DQSN0: U3.G23 U6.B7
DDR_DQSN1: U3.U23 U6.G3
DDR_ODT: R40.1 U3.L22 U6.K1
DDR_RASN: R35.1 U3.N21 U6.J3
DDR_RESETN: R15.1 R102.1 U3.D20 U6.T2
DDR_WEN: R39.1 U3.M20 U6.L3
DSI_CK_N: J2.49 U3.A16
DSI_CK_P: J2.51 U3.B16
DSI_D0_N: J2.55 U3.B15
DSI_D0_P: J2.57 U3.C15
DSI_D1_N: J2.43 U3.A17
DSI_D1_P: J2.45 U3.B17
DSI_LCD_BL_CTRL: J2.65 U3.C19
DSI_LCD_INT: J2.61 U3.A14
DSI_RESET: J2.67 U3.D19
DSI_TE: J2.63 U3.AA19
DVP_D0: J1.46 U3.B14
DVP_D1: J1.48 U3.C2
DVP_D2: J1.50 U3.C4
DVP_D3: J1.52 U3.C8
DVP_D4: J1.54 U3.A4
DVP_D5: J1.56 U3.D14
DVP_D6: J1.58 U3.A3
DVP_D7: J1.60 U3.B10
DVP_HSYNC: J1.62 U3.V4
DVP_PCLK: J1.66 U3.AC8
DVP_VSYNC: J1.64 U3.D11
ETH_CLK: J1.42 U3.AB9
ETH_CLK125: J1.12 U3.Y6
ETH_GTX_CLK: J1.18 U3.AB2
ETH_MDC: J1.32 U3.AA6
ETH_MDINT: J1.40 U3.V2
ETH_MDIO: J1.34 U3.AC3
ETH_NRST: J1.38 U3.AC2
ETH_RX_CLK: J1.14 U3.AA4
ETH_RX_DV: J1.10 U3.AB8
ETH_RXD0: J1.2 U3.AC7
ETH_RXD1: J1.4 U3.AB7
ETH_RXD2: J1.6 U3.AB6
ETH_RXD3: J1.8 U3.AA7
ETH_TX_EN: J1.28 U3.AB1
ETH_TXD0: J1.20 U3.AA2
ETH_TXD1: J1.22 U3.AA1
ETH_TXD2: J1.24 U3.Y2
ETH_TXD3: J1.26 U3.Y1
FDCAN1_RX: J4.68 U3.B8
FDCAN1_TX: J4.70 U3.B9
FDCAN2_RX: J4.64 U3.Y8
FDCAN2_TX: J4.66 U3.AA10
GPIO_PD4: J4.47 U3.B6
GPIO_PE12: J1.70 U3.B4
GPIO_PF3: J4.53 U3.U1
GPIO_PF8: J4.51 U3.AC11
GPIO_PF12: J4.49 U3.Y9
GPIO_PG3: R5.1 U3.T4
GPIO_PG11: J4.55 U3.Y7
GPIO_PI3: J2.39 U3.E1
GPIO_PZ4: J4.45 U3.G2
HDMI_CEC: J1.7 U3.Y14
HDMI_INT: J1.9 U3.W1
HDMI_NRST: J1.11 U3.Y17
HES_OUT: R89.2 R90.2 U3.P2
HSE_IN: R4.2 U3.P1
I2C1_SCL: J4.32 U3.AC4
I2C1_SDA: J4.34 U3.Y4
I2C2_SCL: J2.32 R151.2 U2.4 U3.B3
I2C2_SDA: J2.34 R152.2 U2.3 U3.A2
I2S2_CK: J1.1 U3.Y3
I2S2_SDO: J1.5 U3.W2
I2S2_WS: J1.3 U3.AC5
JTDI: J4.56 U3.A20
JTDO_TRACESWO: J4.58 U3.A19
JTRST: J4.60 U3.B19
LES_OUT: R79.2 U3.L1
LPO_32K: J2.50 U3.L4
LSE_IN: R2.1 U3.L2
LTDC_B0: J1.29 U3.K1
LTDC_B1: J1.27 U3.K4
LTDC_B2: J1.25 U3.AB11
LTDC_B3: J1.23 U3.B5
LTDC_B4: J1.21 U3.E4
LTDC_B5: J1.19 U3.U2
LTDC_B6: J1.17 U3.AB10
LTDC_B7: J1.15 U3.K3
LTDC_CLK: J1.63 U3.AC14
LTDC_DE: J1.65 U3.Y12
LTDC_G0: J1.45 U3.C6
LTDC_G1: J1.43 U3.C10
LTDC_G2: J1.41 U3.D1
LTDC_G3: J1.39 U3.C3
LTDC_G4: J1.37 U3.B1
LTDC_G5: J1.35 U3.C1
LTDC_G6: J1.33 U3.E3
LTDC_G7: J1.31 U3.E2
LTDC_HSYNC: J1.67 U3.T1
LTDC_R0: J1.61 U3.AB4
LTDC_R1: J1.59 U3.AA3
LTDC_R2: J1.57 U3.D5
LTDC_R3: J1.55 U3.C5
LTDC_R4: J1.53 U3.V3
LTDC_R5: J1.51 U3.AB5
LTDC_R6: J1.49 U3.B2
LTDC_R7: J1.47 U3.D3
LTDC_VSYNC: J1.69 U3.H4
MMC2_CLK: R134.1 U3.C9
MMC2_CMD: R133.1 U3.A10
MMC2_DAT0: R125.1 U3.C13
MMC2_DAT1: R126.1 U3.B12
MMC2_DAT2: R127.1 U3.A11
MMC2_DAT3: R128.1 U3.B13
MMC2_DAT4: R129.1 U3.A13
MMC2_DAT5: R130.1 U3.A8
MMC2_DAT6: R131.1 U3.C11
MMC2_DAT7: R132.1 U3.B11
MOC1: J1.68 U3.N2
MOC2: J4.43 U3.T2
NRST: J4.50 R135.1 R153.1 U3.M3
OTG_FS_DM: J2.4 U3.AA18
OTG_FS_DP: J2.2 U3.AB19
OTG_VBUS: J2.8 U3.AC19
PA0_WKUP: J4.44 U2.43 U3.AB3
PMIC_WAKEUP: J4.42 U2.2(WAKEUP) U3.K2
PONKEYN: J4.46 U2.17
PWR_ON: J4.40 R88.1 U2.44 U3.R2
QSPI_BK1_IO0: J2.12 U3.AC10
QSPI_BK1_IO1: J2.14 U3.Y18
QSPI_BK1_IO2: J2.16 U3.AB12
QSPI_BK1_IO3: J2.18 U3.AA13
QSPI_BK2_IO0: J2.20 U3.AA11
QSPI_BK2_IO1: J2.22 U3.AC13
QSPI_BK2_IO2: J2.24 U3.AA9
QSPI_BK2_IO3: J2.26 U3.Y15
QSPI_CLK: J2.28 U3.Y16
SAI2_FSAM: J2.15 U3.F2
SAI2_MCLKA: J2.19 U3.D6
SAI2_SCKAM: J2.13 U3.F3
SAI2_SDAM: J2.17 U3.F4
SAI2_SDBM: J2.21 U3.Y10
SDMMC1_CK: J2.37 U3.D13
SDMMC1_CMD: J2.35 U3.D12
SDMMC1_D0: J2.27 U3.D18
SDMMC1_D1: J2.29 U3.D17
SDMMC1_D2: J2.31 U3.D15
SDMMC1_D3: J2.33 U3.D16
SDMMC3_CLK: J2.70 U3.B7
SDMMC3_CMD: J2.68 U3.A5
SDMMC3_D0: J2.60 U3.D8
SDMMC3_D1: J2.62 U3.D9
SDMMC3_D2: J2.64 U3.A7
SDMMC3_D3: J2.66 U3.D10
SPI1_CLK: J2.40 U3.G3
SPI1_MISO: J2.38 U3.G1
SPI1_MOSI: J2.36 U3.J4
SPI5_CLK: J2.46 U3.Y11
SPI5_MISO: J2.44 U3.W4
SPI5_MOSI: J2.42 U3.AA14
STLINK_SWCLK: J4.54 U3.B20
STLINK_SWDIO: J4.52 U3.C20
STUSB1600_IRQOUTN: J2.6 U3.P4
TIM4_CH3: J4.36 U3.L3
TIM4_CH4: J4.38 U3.J2
USART1_CTS: J2.56 U3.G4
USART1_RTS: J2.58 U3.H2
USART1_RX: J2.54 U3.H1
USART1_TX: J2.52 U3.J3
USART2_RX: J2.1 U3.D2
USART2_TX: J2.3 U3.D7
USB1_N: J4.61 U3.AB17
USB1_P: J4.63 U3.AC17
USB2_N: J4.67 U3.AB16
USB2_P: J4.69 U3.AC16
VREF+: C47.1 J4.31 R94.2 U3.R4
VREF_DDR: C27.1 C53.1 C54.1 C201.1 U2.16 U3.AC20 U6.H1 U6.M8
VTT_DDR: C59.1 C60.1 C61.1 C62.1 C63.1 C64.1 C65.1 C66.1 C67.1 C68.1 C69.1 C70.1 C91.1 C92.1 C93.1 C94.1 C202.1 R17.2 R18.2 R19.2 R20.2 R21.2 R22.2 R23.2 R24.2 R25.2 R26.2 R27.2 R28.2 R29.2 R30.2 R31.2 R32.2 R33.2 R34.2 R35.2 R36.2 R37.2 R38.2 R39.2 R40.2 R119.2 U2.14
N3275089: R13.1 U6.L8(ZQ)
N3282469: R147.1 U8.A6
N3282544: C180.1 U8.C2
N3283232: R125.2 R136.2 U8.A3
N3283236: R126.2 R137.2 U8.A4
N3283240: R127.2 R138.2 U8.A5
N3283244: R128.2 R139.2 U8.B2
N3283248: R129.2 R140.2 U8.B3
N3283252: R130.2 R141.2 U8.B4
N3283256: R131.2 R142.2 U8.B5
N3283260: R132.2 R143.2 U8.B6
N3283264: R133.2 R144.2 U8.M5
N3283268: C179.1 R134.2 R145.2 U8.M6
N3283272: R135.2 R146.2 U8.K5
N3285898: R148.1 U8.J5
N3300775: L9.1 U2.7
N3300820: C196.1 L9.2 R154.1
N3300941: L10.1 U2.11
N3301067: L11.1 U2.29
N3301183: L12.1 U2.25
N3302965: C208.1 U2.40
N3306561: R153.2 U2.1
N3308705: L8.2 U2.33
N3308709: C190.1 L8.1 R149.2
N3309141: R155.1 U2.35
N3309849: R150.2 U2.37
N3309984: R156.1 U2.38
N3317349: C48.2 U3.AB15
N3317353: C49.1 C50.1 R95.2 U3.AB14 U3.C14
N3322011: C51.1 C142.1 U3.C17 U3.C18
N3340590: C46.1 L5.2 R93.2 R94.1 U3.1H1
N3340594: L5.1 R12.2
N3362916: R10.1 U3.K23(DDR_ZQ)
N3364394: TP102.1(TP) U3.Y19
N3364398: TP103.1(TP) U3.K20
N3364402: TP104.1(TP) U3.L21
N3371131: C108.1 OSC1.3 R4.1
N3371139: C106.2 OSC1.4(VDD) R87.2
N3371143: C107.2 OSC1.1 R1.2 R88.2 R90.1
N3374325: R81.1 R82.1 U3.AB13
N3375018: R83.1 R85.2 U3.R3
N3375025: R84.1 R86.2 U3.T3
N3375486: C105.1 U3.M4
N3376367: R80.1 U3.AB18
N3444553: C109.1 R2.2 X1.1
N3444560: C110.1 R79.1 X1.2
N3457313: TP101.1(TP) U3.N3
N3836449: LED2.1 R5.2
N3836598: LED1.1 R6.2 R7.2

Pads without a net: J4 29 30; U3 A21 A22 AA20 AA22 AA23 AB20 AB21 AB22 AB23 AC21 AC22 B21 B22 B23 C22 C23 D21 D22 D23 E23 Y22 Y23; U6 J1 J9 L1 L9; U8 A1 A2 A7 A8 A9 A10 A11 A12 A13 A14 B1 B7 B8 B9 B10 B11 B12 B13 B14 C1 C3 C5 C7 C8 C9 C10 C11 C12 C13 C14 D1 D2 D3 D4 D12 D13 D14 E1 E2 E3 E5 E8 E9 E10 E12 E13 E14 F1 F2 F3 F10 F12 F13 F14 G1 G2 G3 G10 G12 G13 G14 H1 H2 H3 H5 H12 H13 H14 J1 J2 J3 J12 J13 J14 K1 K2 K3 K6 K7 K10 K12 K13 K14 L1 L2 L3 L12 L13 L14 M1 M2 M3 M7 M8 M9 M10 M11 M12 M13 M14 N1 N3 N6 N7 N8 N9 N10 N11 N12 N13 N14 P1 P2 P7 P8 P9 P10 P11 P12 P13 P14

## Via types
v1: diameter 0.356, hole 0.203, TOP to BOTTOM, 734 vias
v2: diameter 0.254, hole 0.102, TOP to GND02, 50 vias
v3: diameter 0.457, hole 0.203, TOP to BOTTOM, 77 vias

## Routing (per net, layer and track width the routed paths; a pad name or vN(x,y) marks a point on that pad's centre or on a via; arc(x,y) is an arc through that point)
1V2_HDMI: length 23.1
  TOP w0.203: U2.21 33.45,31.64 33.61,31.8 33.65,31.8
  TOP w0.356: 34.22,32.1 34.47,32.35 C204.1
  TOP w0.381: 34.22,32.1 v1(34.19,32.07) 33.91,32.07 33.65,31.8
  LAYER_5 w0.381: v1(16.62,36.29) 16.54,36.21 16.54,35.65 16.96,35.23 20.83,35.23 22.52,33.54 23.89,33.54 27.74,33.54 29.39,31.89 33.62,31.89 33.8,32.07 v1(34.19,32.07)
  BOTTOM w0.203: J4.25 v1(16.62,36.29)
1V8_AUDIO: length 19.5
  TOP w0.152: U2.23 32.07,32.95 32.16,33.04 32.39,33.04
  TOP w0.381: v1(32.8,33.04) 32.39,33.04
  LAYER_5 w0.381: v1(17.02,35.93) 17.25,35.7 21.87,35.7 23.52,34.05 28.12,34.05 29.77,32.4 32.16,32.4 v1(32.8,33.04)
  BOTTOM w0.203: J4.23 v1(17.02,35.93)
  BOTTOM w0.381: C203.1 v1(32.8,33.04)
3V3: length 28.9
  TOP w0.152: U2.27 30.47,33.51 30.51,33.54
  TOP w0.203: U8.F5 U8.E6 ; v1(3.68,34.99) 4.23,34.99 6.39,37.14 14.47,37.14 v1(14.69,37.36) ; U8.J10 v1(15,31.24) 15.13,31.12 U8.K9 15.31,31.31 15.31,31.37 15.13,31.55 15.07,31.55 U8.J10
  TOP w0.254: v1(13.97,28.59) 13.95,28.62 13.64,28.62 13.5,28.76 U8.F5
  LAYER_5 w0.203: v1(14.69,37.36) 14.69,36.95 15.05,36.58 15.05,35.74 13.87,34.56 13.87,33.72 15,32.59 v1(15,31.24)
  BOTTOM w0.203: J4.6 v1(20.62,33.29) ; J4.8 20.22,33.37 v1(20.22,33.67) 19.82,33.27 J4.10 ; R7.1 3.33,34.65 v1(3.68,34.99) ; J4.4 21.02,33.51 v1(20.86,33.67) ; J4.2 v1(21.42,33.61)
  vias: v1(32.03,37.1) v1(32.03,36.72) v1(32.54,37.1) v1(32.54,36.72) v1(34.14,32.98)
3V3_HDMI: length 26.6
  TOP w0.203: U2.18 34.17,30.44 v1(34.27,30.34)
  TOP w0.381: v1(34.27,30.34) 34.3,30.32 C205.1
  LAYER_5 w0.356: v1(34.27,30.34) 34.7,30.78
  LAYER_5 w0.381: v1(16.67,36.97) 21.92,36.97 22.94,35.96 24.82,35.96 26.07,34.71 33.46,34.71 34.7,33.47 34.7,30.78
  BOTTOM w0.203: J4.27 16.22,36.53 v1(16.67,36.97)
5V_VIN: length 15.9
  TOP w0.152: U2.12 32.33,27.79 v1(32.41,27.7) ; U2.12 32.07,27.66 32.18,27.55 32.4,27.55 32.41,27.57 v1(32.41,27.7) ; U2.12 32.07,27.87 32.16,27.96 32.31,27.96 32.47,27.8 32.47,27.75 v1(32.41,27.7) ; 26.06,31.89 26.32,31.64 U2.36 ; v1(31.73,33.3) 31.73,33.24 31.71,33.22 31.71,33.22 31.68,33.19 U2.24 ; U2.8 v1(30.47,27.19) ; U2.28 30.07,33.24 30.05,33.26 v1(30.05,33.3) ; U2.19 v1(33.48,30.84)
  TOP w0.305: v1(33.89,30.83) 33.87,30.84 v1(33.48,30.84) ; v1(32.41,27.7) 32.72,27.7 v1(32.8,27.63) ; v1(30.47,27.19) 30.48,27.18 30.48,26.84 30.53,26.79 v1(30.53,26.79) ; v1(31.73,33.3) 31.95,33.52 v1(32.06,33.52) ; v1(30.15,33.67) 30.05,33.57 v1(30.05,33.3)
  TOP w0.381: C194.1 v1(25.26,32.07)
  BOTTOM w0.203: J4.1 21.42,36.01 v1(21.62,36.21) ; J4.7 v1(20.22,36.34) ; J4.11 v1(19.42,36.3) 19.82,35.9 J4.9 ; J4.15 18.62,36.13 v1(18.83,36.34) 18.83,36.03 19.02,35.84 J4.13 ; J4.5 20.62,35.9 v1(21.02,36.3) J4.3
  vias: v1(24.67,35.32) v1(24.67,34.56) v1(25.05,34.56) v1(25.61,31.89)
GND: length 382.2
  TOP w0.076: U8.N2 16.76,27.38 16.76,27.03 16.77,27.03 v1(16.77,26.79)
  TOP w0.089: U3.F21 v2(18.9,14.95) ; v2(18.88,8.95) U3.V21 18.63,8.7 18.63,7.71 v2(18.88,7.45) ; U3.AA8 v2(12.38,7.45) ; U3.C12 v2(14.37,16.45) ; U3.K21 v2(18.88,12.95) ; U3.C7 v2(11.89,16.45) ; U3.H3 v2(9.88,13.96) ; U3.C16 v2(16.38,16.45) ; U3.AA16 v2(16.38,7.48) ; U3.P21 v2(18.88,10.96)
  TOP w0.203: C109.2 3.8,14.17 3.76,14.21 3.28,14.21 v1(3.15,14.34) ; U3.1B6 v1(15.24,14.12) U3.1A7 15.68,15.23 15.65,15.26 ; U3.1B6 U3.1C7 ; U3.1B6 U3.1C5 ; U3.1B2 U3.1C3 13.42,12.92 v1(13.52,12.92) 13.73,12.71 U3.1D4 13.95,12.6 v1(14,12.55) ; U3.1B2 12.43,14.02 v1(12.73,14.31) 12.73,14.32 12.84,14.32 U3.1A3 ; U3.1B2 U3.1C1 ; U2.30 29.28,31.6 29.06,31.38 29.06,31.05 ; v1(8.69,6.16) 8.69,6.26 U3.AC1 ; v1(13.62,30.29) 14,29.91 U8.G5 ; v1(13.62,30.29) 14.5,31.18 U8.H10 ; v1(13.62,30.29) 13.44,30.12 U8.E7 ; U3.1H4 13.73,10.11 v1(13.57,10.28) 13.19,10.65 U3.1G3 U3.1F4 U3.1E3 ; U3.1H4 U3.1G5 v1(14.61,10.43) U3.1H6 U3.1J7 U3.1H8 U3.1G7 15.68,10.82 15.63,10.88 v1(15.63,10.91) ; U3.1H4 U3.1J3 13.09,9.35 ; U8.N5 U8.P6 17.93,29.62 v1(17.94,29.61) 17.94,29.05 U8.P4 ; v1(14,12.55) 14,12.33 U3.1E5 U3.1D6 15.21,12.78 15.22,12.78 v1(15.44,13) 15.68,13.24 U3.1C7 ; v1(14,12.55) 14,12.88 U3.1C5 ; U2.32 28.47,31.64 29.06,31.05 ; v1(13.06,28.59) 12.67,28.98 12.37,28.98 U8.C4 ; U3.1E3 12.91,12.13 12.89,12.13 v1(12.64,12.37) 12.64,12.39 12.63,12.4 12.63,12.41 U3.1D2 ; U3.1E3 U3.1F2 v1(12.2,11.54) U3.1E1 ; U2.26 30.87,31.24 v1(29.87,30.24) ; 15.27,11.4 15.27,11.27 v1(15.63,10.91) ; 15.27,11.4 15.27,11.41 v1(15.27,11.45) ; 15.27,11.4 15.27,11.44 v1(15.27,11.45) ; 33.09,15.03 U6.D1 33.48,15.41 ; v2(16.99,10.63) 16.98,10.65 U3.1G9 16.98,10.77 16.62,11.13 16.5,11.13 U3.1F8 15.94,10.91 v1(15.63,10.91) ; 29.06,31.05 v1(29.87,30.24) ; 30.87,29.24 31.28,28.84 U2.10 ; 30.87,29.24 v1(29.87,30.24) ; 30.87,29.24 U2.15 ; 31.88,8.25 U6.F9 31.49,8.63 ; 29.68,30.04 29.28,29.64 U2.41 ; 29.68,30.04 U2.6 ; 29.68,30.04 v1(29.87,30.24) ; U3.1F6 15.13,11.3 v1(15.27,11.45) ; v1(15.27,11.45) 15.49,11.66 15.49,11.76 U3.1E7 15.99,12.26 15.99,12.59 v1(16.11,12.72) 16.22,12.6 U3.1D8 U3.1E9 ; U3.1C5 U3.1B4 13.94,14.11 13.94,14.32 14.17,14.55 U3.1A5 14.38,14.75 v1(14.25,14.88) ; R89.1 4.07,11.3 3.99,11.38 C110.2 v2(3.97,11.7) ; v1(19.67,6.21) 19.67,6.25 U3.AC23 ; v1(15.96,30.78) 15.8,30.62 U8.K8 ; U3.1H2 v1(11.98,10.46) U3.1G1 ; v1(20.07,18.94) 20.07,17.64 U3.A23 ; U3.1B8 U3.1C7 ; 31.46,8.63 U6.G9 31.08,9.01 ; U3.1C9 v2(16.98,13.26) ; U3.A1 v1(8.66,17.68) ; 23.49,15.03 U6.T1 23.87,15.41
  TOP w0.216: 32.97,18.79 C157.2 33.43,19.19 ; LED2.2 1.94,35.23 ; LED2.2 1.94,34.31 ; LED2.2 1.42,34.77 ; 2.84,7.42 OSC1.2 1.98,8.16 ; 9.91,22.18 C133.1 9.45,21.79 ; 1.94,35.36 LED1.2 ; LED1.2 1.94,36.27 ; LED1.2 1.42,35.81 ; 34.19,36.03 J6.1 36.1,34.13 ; 2.11,17.45 J7.1 ; J7.1 4.01,19.35 ; J7.1 2.11,21.26 ; 31.78,4.36 C149.2 31.32,4.75 ; 36.07,3.85 J5.1 34.17,1.95 ; 32.8,4.36 C150.2 33.25,4.75 ; 35.49,29.86 C205.2 35.89,30.32 ; 35.54,28.27 C202.2 ; C202.2 36.09,27.69 ; C202.2 36.64,28.27 ; 24.1,27.93 C195.2 23.7,28.39 ; C201.2 35.86,29.35 ; C201.2 35.47,28.9 ; C201.2 35.47,29.81 ; 36.17,4.75 C153.2 35.26,4.75 ; 35.53,27 C191.2 ; C191.2 36.64,27 ; C191.2 36.09,26.42 ; C191.2 36.09,27.59 ; 34.7,4.36 C152.2 35.16,4.75
  TOP w0.254: v1(34.81,19.78) 34.81,19.39 35.4,18.79 ; 35.4,18.79 C156.2 34.21,18.79 v1(33.94,19.06) 33.67,18.79 C157.2 ; 35.4,18.79 C155.2 C154.2 ; v1(20.52,21.02) 20.52,20.46 20.32,20.26 20.32,19.52 20.07,19.27 v1(20.07,18.94)
  TOP w0.305: U6.T1 v1(23.5,15.4) ; R15.2 23.42,18.74 v1(22.86,19.29) ; v1(31.39,18.9) 31.03,18.9 30.94,18.81 C54.2 29.7,18.81 v1(29.44,19.07) 29.19,18.81 C82.2 ; C53.2 C147.2 ; v1(25.38,19.04) 25.68,18.74 C80.2 26.25,18.74 v1(26.58,19.06) ; 1.39,7.44 v1(0.84,7.99)
  TOP w0.356: v3(31.48,15.43) U6.G1 ; v3(33.08,14.63) U6.E2 ; v3(25.07,15.43) U6.P1 ; v3(25.07,8.23) U6.P9 ; v3(35.48,13.83) U6.B3 ; v3(35.48,15.43) U6.B1 ; v3(31.48,8.23) U6.G9 ; v3(26.67,15.43) U6.M1 ; v3(31.48,9.03) U6.G8 ; v3(33.88,15.43) U6.D1 ; v3(23.47,8.23) U6.T9 ; v3(29.07,14.63) U6.J2 ; v3(36.28,8.23) U6.A9 ; v3(33.88,9.03) U6.D8 ; v3(35.48,8.23) U6.B9 ; v3(26.67,8.22) U6.M9 ; v3(32.28,8.23) U6.F9 ; v3(33.08,9.03) U6.E8 ; v3(29.07,9.03) U6.J8 ; v3(33.08,15.43) U6.E1
  TOP w0.381: v1(9.78,22.44) 9.78,21.91 C133.1 ; C147.2 25.94,4.49 v1(26.14,4.28) ; C82.2 v1(28.1,18.81) ; R10.2 22.23,13.61 v1(22.59,13.96) ; v1(32.28,4.33) 32.2,4.33 C149.2 C150.2 ; v1(33.83,4.36) 33.81,4.37 C151.2 C152.2 ; v1(30.84,4.36) 30.84,4.41 30.82,4.44 R14.1 ; v1(4.73,4.72) 4.83,4.61 C108.2 ; C107.1 2.51,7.95 OSC1.2 1.42,7.42 1.39,7.44 ; v1(28.78,3.85) 28.78,4.06 28.86,4.14 C148.2 R13.2 C53.2 26.95,4.69 v1(27.28,4.36) ; C194.2 v1(23.73,32.07) ; C81.2 v1(25.05,3.98) ; C202.2 v1(36.09,28.96) ; C153.2 v1(35.72,4.16)
  GND02 w0.203: v1(18.94,18.03) 18.94,17.73 18.88,17.67 v2(18.88,16.42)
  GND02 w0.254: v2(14.37,16.45) 14.37,17.02 13.9,17.49 13.9,19.42 14.21,19.73 v1(14.33,19.73) ; v1(17.3,17.92) 17.3,17.87 16.88,17.45 16.88,17.43 16.38,16.93 v2(16.38,16.45) ; v1(19.74,4.56) 19.74,6.14 v1(19.67,6.21)
  GND02 w0.47: 2.11,17.45 J7.1 ; J7.1 2.11,21.26 ; J7.1 4.01,19.35 ; 34.17,1.95 J5.1 36.07,3.85 ; 36.1,34.13 J6.1 34.19,36.03
  LAYER_3 w0.47: 2.11,17.45 J7.1 ; J7.1 4.01,19.35 ; J7.1 2.11,21.26 ; 34.17,1.95 J5.1 36.07,3.85 ; 36.1,34.13 J6.1 34.19,36.03
  LAYER_5 w0.47: 36.1,34.13 J6.1 34.19,36.03 ; 36.07,3.85 J5.1 34.17,1.95 ; 2.11,17.45 J7.1 2.11,21.26
  LAYER_6 w0.47: 36.07,3.85 J5.1 34.17,1.95 ; 4.01,19.35 J7.1 2.11,21.26 ; 34.19,36.03 J6.1 36.1,34.13
  GND7 w0.47: 34.17,1.95 J5.1 36.07,3.85 ; 36.1,34.13 J6.1 34.19,36.03 ; J7.1 4.01,19.35 ; J7.1 2.11,21.26 ; J7.1 2.11,17.45
  BOTTOM w0.127: C46.2 11.31,10.28 11.08,10.51 ; 17.12,11.22 17.12,10.56 17.23,10.46 17.23,10.08 17.2,10.05 17.2,9.77 16.92,9.49 16.86,9.49
  BOTTOM w0.152: C120.2 16.79,12.02 17.12,11.68 17.12,11.22
  BOTTOM w0.203: J2.59 19.43,20.47 v1(19.68,20.22) ; 16.3,9.67 16.3,9.51 16.31,9.49 ; 16.3,9.67 16.04,9.41 ; 16.3,9.67 16.3,10.42 16,10.72 C42.2 ; 16.31,9.49 16.23,9.41 16.04,9.41 ; 16.31,9.49 C44.2 16.86,9.49 17.06,9.29 17.14,9.29 17.25,9.19 ; J2.25 v1(12.63,22.32) ; C182.2 12.35,31.03 v1(12.5,31.18) 12.22,31.46 J4.48 ; C182.2 12.81,30.75 ; C182.2 11.89,30.75 ; J4.41 v1(13.42,36.19) ; J4.65 v1(8.62,35.89) ; C185.2 17.63,27.12 ; C185.2 17.18,26.72 ; C185.2 16.97,27.12 16.77,26.91 v1(16.77,26.79) ; v1(14.61,10.43) 14.87,10.16 C36.2 ; C29.2 16.04,9.41 ; J4.62 9.42,33.68 v1(9.05,34.05) ; v1(0.87,16.5) 0.96,16.41 J1.72 ; v1(15.17,23.46) 15.83,22.8 J2.41 ; v1(17.03,20.9) 17.03,21.2 17.03,21.2 J2.47 ; 21.89,22.28 21.78,22.4 21.57,22.4 21.43,22.25 J2.69 21.43,21.29 21.14,21 20.85,21 20.83,21.02 v1(20.52,21.02) ; 21.89,22.28 21.92,22.25 21.92,21.7 J2.71 ; 21.89,22.28 21.89,23.69 21.9,23.7 J2.72 22.21,24.39 22.26,24.34 v1(22.31,24.34) ; J1.71 4.15,16.74 4.24,16.82 v1(4.24,16.83) ; 12.94,11.95 C105.2 ; C105.2 12.22,11.57 v1(12.2,11.54) ; C105.2 12.22,12.91 C28.2 ; v1(15.27,11.45) 15.05,11.45 14.78,11.72 14.71,11.72 14.52,11.92 C35.2 ; J1.30 0.9,7.93 v1(0.84,7.99) ; J2.53 v1(18.23,22.51) ; C137.2 16.85,16.84 17.28,16.84 17.54,16.58 C138.2 ; J2.10 v1(9.43,25.16) ; C28.2 12.25,12.76 v1(12.64,12.37) 12.97,12.04 C31.2 ; C28.2 12.94,12.94 C32.2 13.35,13.09 v1(13.52,12.92) 13.69,13.09 C33.2 ; 4.75,4.73 4.81,4.73 ; 4.75,4.73 v1(4.73,4.72) ; 4.75,4.73 J1.13 ; J4.57 10.22,36.2 v1(10.11,36.31) 9.82,36.02 v1(9.82,35.94) J4.59 ; 16.85,12.72 16.56,13 C43.2 16.39,13 v1(16.11,12.72) ; 16.85,12.72 16.92,12.72 ; 16.85,12.72 16.81,12.68 16.26,12.68 16.22,12.72 v1(16.11,12.72) ; v1(15.44,13) 15.51,13.06 15.83,13.06 15.83,13 v1(16.11,12.72) ; 16.08,12.68 v1(16.11,12.72) ; J1.74 v1(0.96,1.86) ; v1(12.73,14.31) 12.5,14.09 12.5,13.96 12.37,13.83 C30.2 ; v1(13.41,25.26) 13.41,24.95 13.43,24.93 J2.30 ; C37.2 13.69,10.16 v1(13.57,10.28) 13.43,10.14 C39.2 ; J1.16 v1(0.88,5.13) ; J2.11 9.83,22.38 9.78,22.43 v1(9.78,22.44) ; J1.36 1.83,9.13 1.99,9.29 v1(2,9.29) ; v1(14.69,36.32) 14.69,36.31 14.62,36.25 J4.35 ; 12.48,28.26 C180.2 11.89,28.81 ; J4.73 v1(21.9,34.81) ; J2.48 17.03,25.11 17.07,25.16 17.07,25.16 17.28,25.37 v1(17.69,25.77) ; J1.44 0.82,10.73 0.79,10.71 v1(0.76,10.71) ; J2.73 J2.74 7.35,24.77 v1(7.17,24.96) ; J4.74 v1(21.9,33.16) ; J1.73 v1(4.69,1.86)
  BOTTOM w0.216: 34.4,18.65 C70.2 33.48,18.65 ; 6.97,35.35 J4.71 7.35,34.82 ; 30.8,18.23 C93.2 ; C93.2 31.97,18.23 ; C93.2 31.39,17.68 ; 31.22,35.7 C199.2 30.61,34.86 ; 36.07,3.85 J5.1 34.17,1.95 ; 31.97,19.5 C94.2 30.8,19.5 ; 6.97,32.64 J4.72 7.35,33.17 ; 25.51,4.46 C60.2 24.59,4.46 ; J7.1 2.11,21.26 ; J7.1 4.01,19.35 ; J7.1 2.11,17.45 ; 29.37,24.93 C196.2 29.98,25.77 ; 32.49,24.96 C197.2 33.1,25.8 ; 30.29,5.04 C91.2 30.87,5.59 ; 26.57,35.4 C190.2 25.99,34.85 ; 19.51,28.72 C181.2 20.12,27.88 ; 34.19,36.03 J6.1 36.1,34.13 ; 29.37,32.15 C200.2 28.15,32.15 ; 22.81,4.46 C64.2 23.73,4.46 ; 22.28,32.64 J4.74 21.9,32.11 ; 16.97,2.03 C52.2 17.43,2.43
  BOTTOM w0.254: v1(12.73,14.31) 13.1,14.68 13.1,15.01 13.21,15.13 C49.2 ; C35.2 14.52,12.22 14.33,12.41 14.14,12.41 v1(14,12.55) 13.97,12.58 C33.2 14.03,13.09 14.58,13.64 14.64,13.64 14.86,13.86 C34.2 ; C50.2 15.86,15.63 v1(15.98,15.51) 16.11,15.64 C51.2 ; 14.33,10.16 C37.2 ; 14.33,10.16 v1(14.61,10.43) ; 14.33,10.16 14.41,10.16 14.47,10.1 14.74,10.1 14.8,10.16 14.91,10.16 C36.2 15.04,10.29 15.04,10.81 C40.2 ; C38.2 12.26,10.14 13.13,10.14 C39.2 13.12,10.16 13.12,10.87 12.91,11.08 C41.2 12.59,11.14 v1(12.2,11.54) ; v1(15.24,14.12) 15.24,14.11 15.44,13.92 v1(15.44,13) ; v1(22,1.77) 21.77,2 21.77,2.04 19.74,4.07 v1(19.74,4.56) ; C30.2 12.24,13.36 12.25,13.35 C28.2
  BOTTOM w0.305: C65.2 C63.2 C61.2 C59.2 C62.2 27.94,18.65 v1(28.1,18.81) 28.45,18.81 28.62,18.65 C68.2 ; v1(36.61,22.24) 35.64,21.28 C162.2 36.3,19.78 v1(36.45,19.62) ; C29.2 15.79,9.41 15.56,9.65 15.49,9.65 14.98,10.16 C36.2 ; J4.72 7.35,32 v1(7.24,31.89) ; C52.2 v1(16.34,2.43) ; C50.2 15.56,15.2 15.56,15.19 C121.2 15.93,14.75 C142.2 C51.2 16.41,16.07 16.41,16.07 16.41,16.4 16.54,16.53 C137.2 ; C94.2 31.39,20.78 v1(31.73,21.12) ; C93.2 v1(31.39,18.9) ; C42.2 15.81,11.09 v1(15.63,10.91) 15.53,11.01 C40.2 ; v1(20.07,18.94) 20.07,17.9 18.76,16.58 C138.2 ; C41.2 12.91,11.92 C31.2 ; 12.96,16.02 13.21,15.76 ; 13.21,15.76 C49.2 ; 13.21,15.76 13.21,16.09 13.36,16.25 ; C67.2 26.32,4.46 v1(26.14,4.28) ; C179.2 12.02,16.1 12.02,16.09 ; C69.2 C66.2 ; 15.65,6.95 15.65,6.95 C132.2 ; C48.1 15.78,1.92 ; C92.2 30.87,2.32 31.02,2.18 v1(31.02,1.82) ; v1(13.06,28.59) 12.84,28.81 C180.2 ; J4.71 v1(7.35,35.98) ; R147.2 v1(4.47,36.13)
  BOTTOM w0.356: C47.2 9.83,11.7 9.17,11.04 9.17,8.78 8.79,8.4 8.41,8.4
  BOTTOM w0.381: C60.2 v1(25.05,3.98) ; C27.2 18.52,4.76 18.52,4.36 v1(18.55,4.33) ; C92.2 30.87,4.32 v1(30.84,4.36) 30.87,4.39 C91.2 ; C64.2 v1(23.27,3.83) ; C43.2 16.79,12.75 C120.2 ; 15.22,7.38 15.47,7.64 C132.2 C45.2 15.65,8.93 15.6,8.98 15.7,9.08 15.7,9.26 C29.2 ; C94.2 v1(31.39,18.9) ; C79.2 35.74,4.18 v1(35.72,4.16) ; v1(20.72,29.25) 20.18,28.72 C181.2 20.12,29.25 v1(20.48,29.61) ; C179.2 11.69,16.58 10.59,17.68 v1(8.66,17.68) ; v1(16.77,26.79) 16.48,27.08 C183.2 ; v1(7.28,8.35) 7.28,7.89 6.95,7.56 R85.1 6.58,6.8 R86.1 ; C69.2 27.39,4.46 v1(27.28,4.36) 27.18,4.46 C67.2 ; C68.2 v1(29.44,19.07) ; v1(5.74,3.55) 5.57,3.72 C106.1 ; C59.2 v1(26.58,19.06) ; C46.2 11.66,10.46 v1(11.98,10.46) 12.25,10.18 C38.2 ; R80.2 v1(17.56,4.23) ; v1(16.34,2.43) C48.1 R82.2 ; v1(28.78,3.85) 28.6,4.03 C66.2 ; C65.2 22.89,19.27 v1(22.86,19.29) ; C61.2 25.38,18.96 v1(25.38,19.04) ; C184.2 13.59,30.32 v1(13.62,30.29) R148.2 ; C70.2 v1(33.94,19.06) 34.22,19.34 34.37,19.34 v1(34.81,19.78) C162.2 ; C134.1 v1(12.48,1.96) ; C121.2 15.56,14.44 v1(15.24,14.12) 14.98,13.86 C34.2
  vias: v1(0.54,37.35) v1(0.54,35.58) v1(0.54,33.29) v1(0.54,31.26) v1(0.54,28.85) v1(0.54,26.81) v1(0.54,24.91) v1(0.54,22.88) v1(0.54,21.1) v1(0.54,17.29) v1(0.54,4.59) v1(0.54,2.68) v1(0.54,0.52) v1(1.81,0.52) v1(2.44,37.35) v1(4.22,37.35) v1(5.62,37.35) v1(13.34,21.07) v1(15.65,37.48) v1(17.17,37.48) v1(23.65,29.48) v1(23.65,28.72) v1(24.67,37.35) v1(25.4,23) v1(26.83,0.52) v1(27.46,37.35) v1(27.72,23) v1(28.6,28.85) v1(28.73,31.31) v1(28.73,23) v1(28.73,0.52) v1(28.86,30.24) v1(29.37,31.26) v1(29.49,37.35) v1(30.38,30.24) v1(30.38,23) v1(30.51,0.52) v1(30.64,37.35) v1(30.64,36.59) v1(31.91,23) v1(32.41,0.52) v1(32.92,23.64) v1(32.92,23) v1(33.81,37.23) v1(33.94,35.45) v1(34.19,0.52) v1(34.7,24.4) v1(35.46,33.8) v1(36.61,26.18) v1(36.61,24.4) v1(36.73,33.8) v1(36.73,32.02) v1(36.73,30.37) v1(36.73,28.46) v1(37.37,21.23) v1(37.49,9.92) v1(37.49,8.02) v1(37.49,6.37) v1(37.49,4.21) v2(9.88,10.94) v2(9.88,8.45) v2(10.39,15.97) v2(10.88,7.45) v2(14.41,9.31) v2(14.38,7.45)
VBAT: length 36
  TOP w0.203: U3.1F1 v1(12.01,11.08)
  TOP w0.381: R3.2 v1(10.44,21.02) C133.2
  PWR_4 w0.356: v1(16.22,34.09) 14.91,32.78 12.48,32.78 11.92,32.22 11.92,27.75 9.87,25.71 9.87,24.85 9.32,24.29 9.32,21.74 10.04,21.02 v1(10.44,21.02) 11.28,21.02 11.84,20.46 11.84,18.94 10.23,17.33 10.23,11.45 10.58,11.09 11,11.09 11.11,11.2 11.5,11.2 11.63,11.08 v1(12.01,11.08)
  BOTTOM w0.203: J4.26 v1(16.62,34.1) 16.23,34.1 v1(16.22,34.09) J4.28
VBUS_OTG: length 8.9
  TOP w0.508: R155.2 v1(23.7,33.09)
  LAYER_3 w0.508: v1(18.22,33.67) 18.42,33.67 18.98,34.23 22.56,34.23 v1(23.7,33.09)
  BOTTOM w0.203: J4.16 18.62,33.37 18.48,33.51 18.38,33.51 v1(18.22,33.67) J4.18
VBUS_SW: length 4.9
  BOTTOM w0.203: J4.24 17.02,33.77 v1(17.3,34.05) ; v1(17.3,34.05) 17.31,34.04 v1(17.82,34.04) J4.20 ; v1(17.3,34.05) 17.3,33.75 17.42,33.63 J4.22
  vias: v1(23.02,32.02) v1(23.02,31.51)
VDD: length 76
  TOP w0.152: U2.31 28.87,33.65 ; 26.21,29.24 U2.42
  TOP w0.203: v1(17.94,28.46) 17.59,28.12 U8.P3 U8.N4 17.32,28.94 U8.P5 ; v1(14.08,8.93) 14.08,8.98 13.73,9.33 U3.1J4 U3.1H5 14.56,9.83 v1(14.56,9.69) 14.9,9.35 U3.1J6 ; U3.1H3 13.02,10 v1(12.68,9.67) 12.68,9.6 U3.1J2 ; U3.B18 17.38,17.18 v1(17.28,17.29) ; v1(12.35,29.66) 12.31,29.62 U8.C6 ; U3.1F3 U3.1G2 12.6,10.65 v1(12.72,10.53) ; U3.1G4 v1(14,10.92) ; U8.M4 v1(16.21,28.62)
  TOP w0.381: v1(10.24,22.98) 10.63,22.98 10.93,22.69 R3.1 ; 26.21,29.24 26.11,29.24 v1(25.25,28.39) C195.1 ; R12.1 12.61,3.8 v1(12.48,3.93) ; R1.1 4.82,8.7 6.02,7.49 v1(6.02,6.76) ; R152.1 R151.1 v1(27.01,24.2)
  LAYER_3 w0.381: v1(27.01,24.2) 27.01,24.96 27.46,25.42 27.46,27.7 28.1,28.34 v1(28.1,36.59)
  BOTTOM w0.089: v1(12.72,10.53) 12.72,10.6
  BOTTOM w0.203: C39.1 13.68,9.38 ; 13.68,9.38 13.87,9.19 ; 13.68,9.38 14.02,9.38 C37.1 14.03,9.34 13.87,9.19 ; v1(14.08,8.93) 14.08,8.98 13.87,9.19 ; C38.1 12.39,9.38 v1(12.68,9.67) ; C40.1 14.09,11.01 v1(14,10.92) ; J4.12 19.42,33.34 19.25,33.52 v1(19.25,33.63) 19.03,33.41 19.03,33.37 19.02,33.36 J4.14 ; v1(14.56,9.69) 14.86,9.4
  BOTTOM w0.254: R146.1 15.64,27.07 15.82,27.24 15.82,27.66 16,27.85 C183.1 ; v1(12.68,9.67) 12.97,9.38 C39.1 ; C36.1 14.73,9.4 14.7,9.36 14.42,9.36 14.4,9.39 14.25,9.39 ; C37.1 14.25,9.39 ; 14.25,9.39 v1(14.56,9.69)
  BOTTOM w0.305: 13.49,6.98 13.87,7.36 ; v1(14,10.92) 13.78,11.14 C41.1 ; 13.09,7.36 13.49,6.95
  BOTTOM w0.381: 6.41,31.78 6.02,32.17 R138.1 ; 6.41,31.78 6.41,30.83 ; 6.41,31.78 6.41,32.69 6.43,32.72 6.43,33.26 v1(5.88,33.81) R143.1 ; R137.1 5.97,29.07 6.41,28.64 ; 6.41,28.64 6.41,26.94 ; 6.41,28.64 6.41,30.83 ; 6.41,26.94 6.41,25.54 6.35,25.49 ; 6.41,26.94 5.97,27.37 R141.1 ; 6.35,25.49 6.12,25.73 R136.1 ; 6.35,25.49 6.39,25.46 6.39,24.54 6.01,24.15 v1(5.87,24.15) R140.1 ; R95.1 15.65,17 15.96,17.3 C137.1 17.26,17.3 v1(17.28,17.29) 17.44,17.29 17.5,17.35 C138.1 ; C185.1 16.32,27.88 C183.1 16.29,28.54 v1(16.21,28.62) ; R139.1 5.81,22.59 v1(6.13,22.9) ; v1(14.79,30.78) 14.69,30.88 C184.1 ; R144.1 22.51,28.72 R145.1 v1(22.51,29.18) ; 6.41,30.83 6.17,30.59 v1(5.77,30.59) R142.1 ; R6.1 v1(3.33,33.17) ; C182.1 v1(12.35,29.66) ; 13.49,7.26 13.49,5.83 12.7,5.05 12.7,4.96 12.55,4.8 12.55,4 v1(12.48,3.93) C134.2 12.48,3.57 12.98,3.57 13.24,3.32 13.24,2.68 13.49,2.43 R81.2 ; R83.2 5.57,7.52 R84.2 v1(6.02,6.76) ; C181.1 18.19,28.72 v1(17.94,28.46) ; v1(6.22,3.54) 6.22,3.55 6.23,3.55 6.23,3.67 6.56,4 R87.1
  vias: v1(28.1,36.97) v1(28.6,36.97) v1(28.6,36.59)
